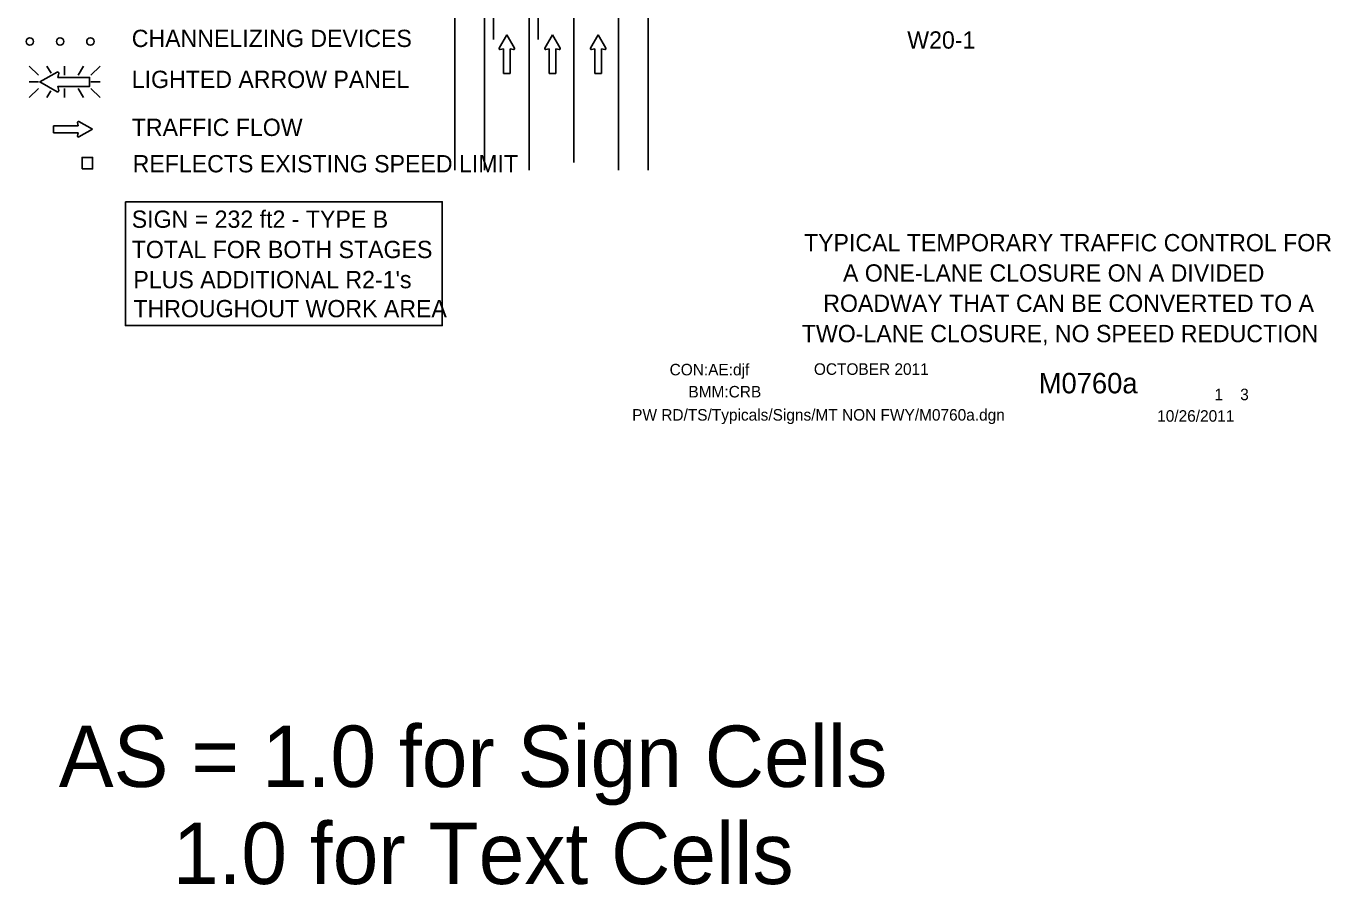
# Model space of a CAD drawing. Extents: x 16735 to 19504, y 6970 to 8243.
# Drawn here: x 16745 to 17446, y 6970 to 7432 of the extents above; entities that cross this region are included whole.
import ezdxf

# ---------------------------------------------------------------- set-up
doc = ezdxf.new("R2010")
doc.units = 0
for name, color, linetype in [('ALI_LEGAL_EX', 7, 'Continuous'), ('BORDER', 7, 'Continuous'), ('BORDER_SIGNAL_WO', 7, 'Continuous'), ('MT_SCRATCH_LEVEL_E', 7, 'Continuous'), ('PAVT_EDGE_EX', 7, 'Continuous'), ('TRAFFIC_SIGNS_PR', 7, 'Continuous'), ('TYPICAL_TEXT_DIMEN_EX', 7, 'Continuous')]:
    doc.layers.add(name, color=color, linetype=linetype)

msp = doc.modelspace()

# ---------------------------------------------------------------- linework, layer by layer
at = {"layer": 'ALI_LEGAL_EX'}
for p, q in [((16995.95, 8243.16), (16995.95, 7425.02)), ((17019.95, 8243.16), (17019.95, 7425.02))]:
    msp.add_line(p, q, dxfattribs=at)
for points in [[(17015.15, 7383.87), (17015.15, 7358.87)], [(17039.15, 7358.87), (17039.15, 7383.87)]]:
    msp.add_lwpolyline(points, dxfattribs=at)
at = {"layer": 'MT_SCRATCH_LEVEL_E'}
for p, q in [((17003.12, 7427.51), (16999.01, 7420.27)), ((17003.12, 7427.51), (16999.01, 7420.27)), ((17007.27, 7420.27), (17003.12, 7427.51)), ((17007.27, 7420.27), (17003.12, 7427.51)), ((17027.68, 7427.51), (17023.57, 7420.27)), ((17027.68, 7427.51), (17023.57, 7420.27)), ((17031.83, 7420.27), (17027.68, 7427.51)), ((17031.83, 7420.27), (17027.68, 7427.51)), ((17052.24, 7427.51), (17048.13, 7420.27)), ((17052.24, 7427.51), (17048.13, 7420.27)), ((17056.39, 7420.27), (17052.24, 7427.51)), ((17056.39, 7420.27), (17052.24, 7427.51)), ((16999.49, 7419.59), (17001.27, 7419.9)), ((16999.49, 7419.59), (17001.27, 7419.9)), ((17001.27, 7419.9), (17001.27, 7406.65)), ((17001.27, 7419.9), (17001.27, 7406.65)), ((17005.01, 7406.65), (17005.01, 7419.9)), ((17005.01, 7419.9), (17006.79, 7419.59)), ((17005.01, 7406.65), (17005.01, 7419.9)), ((17005.01, 7419.9), (17006.79, 7419.59)), ((17024.05, 7419.59), (17025.83, 7419.9)), ((17024.05, 7419.59), (17025.83, 7419.9)), ((17025.83, 7419.9), (17025.83, 7406.65)), ((17025.83, 7419.9), (17025.83, 7406.65)), ((17029.57, 7406.65), (17029.57, 7419.9)), ((17029.57, 7419.9), (17031.35, 7419.59)), ((17029.57, 7406.65), (17029.57, 7419.9)), ((17029.57, 7419.9), (17031.35, 7419.59)), ((17048.61, 7419.59), (17050.39, 7419.9)), ((17048.61, 7419.59), (17050.39, 7419.9)), ((17050.39, 7419.9), (17050.39, 7406.65)), ((17050.39, 7419.9), (17050.39, 7406.65)), ((17054.13, 7406.65), (17054.13, 7419.9)), ((17054.13, 7419.9), (17055.91, 7419.59)), ((17054.13, 7406.65), (17054.13, 7419.9)), ((17054.13, 7419.9), (17055.91, 7419.59)), ((17001.27, 7406.65), (17005.01, 7406.65)), ((17001.27, 7406.65), (17005.01, 7406.65)), ((17025.83, 7406.65), (17029.57, 7406.65)), ((17025.83, 7406.65), (17029.57, 7406.65)), ((17050.39, 7406.65), (17054.13, 7406.65)), ((17050.39, 7406.65), (17054.13, 7406.65)), ((16772.58, 7378.55), (16759.32, 7378.55)), ((16759.32, 7378.55), (16759.32, 7374.81)), ((16772.58, 7378.55), (16759.32, 7378.55)), ((16759.32, 7378.55), (16759.32, 7374.81)), ((16772.26, 7380.33), (16772.58, 7378.55)), ((16772.26, 7380.33), (16772.58, 7378.55)), ((16780.19, 7376.7), (16772.95, 7380.81)), ((16780.19, 7376.7), (16772.95, 7380.81)), ((16772.95, 7372.56), (16780.19, 7376.7)), ((16772.95, 7372.56), (16780.19, 7376.7)), ((16759.32, 7374.81), (16772.58, 7374.81)), ((16759.32, 7374.81), (16772.58, 7374.81)), ((16772.58, 7374.81), (16772.26, 7373.03)), ((16772.58, 7374.81), (16772.26, 7373.03))]:
    msp.add_line(p, q, dxfattribs=at)
for centre, start, end in [((16999.42, 7420.05), 150.42484, 279.96381), ((16999.42, 7420.05), 150.42484, 279.96381), ((17006.86, 7420.05), 260.03619, 29.77312), ((17006.86, 7420.05), 260.03619, 29.77312), ((17023.98, 7420.05), 150.42484, 279.96381), ((17023.98, 7420.05), 150.42484, 279.96381), ((17031.42, 7420.05), 260.03619, 29.77312), ((17031.42, 7420.05), 260.03619, 29.77312), ((17048.54, 7420.05), 150.42484, 279.96381), ((17048.54, 7420.05), 150.42484, 279.96381), ((17055.98, 7420.05), 260.03619, 29.77312), ((17055.98, 7420.05), 260.03619, 29.77312), ((16772.72, 7380.4), 60.42484, 189.96381), ((16772.72, 7380.4), 60.42484, 189.96381), ((16772.72, 7372.96), 170.03619, 299.77312), ((16772.72, 7372.96), 170.03619, 299.77312)]:
    msp.add_arc(centre, 0.463, start, end, dxfattribs=at)
at = {"layer": 'PAVT_EDGE_EX'}
for p, q in [((16975.15, 8183.87), (16975.15, 7354.69)), ((16991.15, 8183.87), (16991.15, 7354.69)), ((17015.15, 8183.87), (17015.15, 7354.69)), ((17039.15, 7358.87), (17039.15, 8183.87)), ((17063.15, 8183.87), (17063.15, 7354.69)), ((17079.15, 8183.87), (17079.15, 7354.69))]:
    msp.add_line(p, q, dxfattribs=at)
at = {"layer": 'TRAFFIC_SIGNS_PR'}
for p, q in [((16746.22, 7410.71), (16751.15, 7405.78)), ((16757.98, 7406.89), (16755.78, 7410.71)), ((16765.3, 7405.78), (16765.3, 7410.71)), ((16772.54, 7405.78), (16775.39, 7410.71)), ((16779.45, 7405.78), (16784.39, 7410.71)), ((16751.15, 7402.22), (16746.22, 7402.22)), ((16746.22, 7393.73), (16751.15, 7398.66)), ((16755.73, 7393.73), (16757.85, 7397.39)), ((16765.3, 7398.66), (16765.3, 7393.73)), ((16775.43, 7393.73), (16772.58, 7398.66)), ((16779.45, 7402.22), (16784.39, 7402.22)), ((16779.45, 7398.66), (16784.39, 7393.73))]:
    msp.add_line(p, q, dxfattribs=at)
for points in [[(16761.23, 7407.5), (16751.94, 7402.22), (16761.23, 7396.9)], [(16762.11, 7397.53), (16761.71, 7399.8), (16778.72, 7399.8), (16778.72, 7404.6), (16761.71, 7404.6), (16762.11, 7406.88)]]:
    msp.add_lwpolyline(points, dxfattribs=at)
msp.add_lwpolyline([(16774.7, 7355.37), (16780.29, 7355.37), (16780.29, 7361.54), (16774.7, 7361.54)], close=True, dxfattribs=at)
for centre in [(16746.56, 7423.91), (16762.86, 7423.91), (16779.16, 7423.91)]:
    msp.add_circle(centre, 2, dxfattribs=at)
for centre, radius, start, end in [((16761.52, 7406.97), 0.598, 350.73078, 118.89165), ((16761.52, 7397.42), 0.597, 241.48329, 9.95933)]:
    msp.add_arc(centre, radius, start, end, dxfattribs=at)
at = {"layer": 'TYPICAL_TEXT_DIMEN_EX'}
msp.add_lwpolyline([(16797.97, 7337.73), (16968.38, 7337.73), (16968.38, 7271.08), (16797.97, 7271.08)], close=True, dxfattribs=at)

# ---------------------------------------------------------------- texts
at = {"layer": 'BORDER'}
for s, p in [('TYPICAL TEMPORARY TRAFFIC CONTROL FOR', (17162.96, 7311.05)), ('A ONE-LANE CLOSURE ON A DIVIDED', (17183.94, 7294.75)), ('ROADWAY THAT CAN BE CONVERTED TO A', (17173.33, 7278.45)), ('TWO-LANE CLOSURE, NO SPEED REDUCTION ', (17161.79, 7262.15))]:
    msp.add_text(s, height=9.3, dxfattribs=at).set_placement(p)
at = {"layer": 'BORDER_SIGNAL_WO'}
for s, height, p in [('CON:AE:djf', 6.2, (17090.69, 7244.31)), ('    OCTOBER 2011    ', 6.2, (17159.08, 7244.59)), ('    M0760a   ', 11, (17272.86, 7234.63)), ('BMM:CRB   ', 6.2, (17100.81, 7232.42)), (' 1    3 ', 6.2, (17381.45, 7230.95)), ('PW RD/TS/Typicals/Signs/MT NON FWY/M0760a.dgn    ', 6.2, (17070.55, 7219.96)), ('10/26/2011    ', 6.2, (17352.93, 7219.38)), ('AS = 1.0 for Sign Cells', 33.0301, (16762.16, 7022.87)), ('     1.0 for Text Cells', 33.0301, (16762.16, 6970.64))]:
    msp.add_text(s, height=height, dxfattribs=at).set_placement(p)
at = {"layer": 'TRAFFIC_SIGNS_PR'}
msp.add_text('W20-1', height=9.3, dxfattribs=at).set_placement((17218.51, 7420.09))
at = {"layer": 'TYPICAL_TEXT_DIMEN_EX'}
for s, p in [('CHANNELIZING DEVICES', (16801.4, 7420.96)), ('LIGHTED ARROW PANEL', (16801.4, 7398.91)), ('TRAFFIC FLOW', (16801.4, 7373.11)), ('REFLECTS EXISTING SPEED LIMIT', (16801.87, 7353.53)), ('SIGN = 232 ft2 - TYPE B', (16801.4, 7323.69)), ('TOTAL FOR BOTH STAGES', (16801.4, 7307.39)), ("PLUS ADDITIONAL R2-1's", (16802.28, 7291.17)), ('THROUGHOUT WORK AREA', (16802.28, 7275.57))]:
    msp.add_text(s, height=9.3, dxfattribs=at).set_placement(p)

doc.saveas('drawing.dxf')
